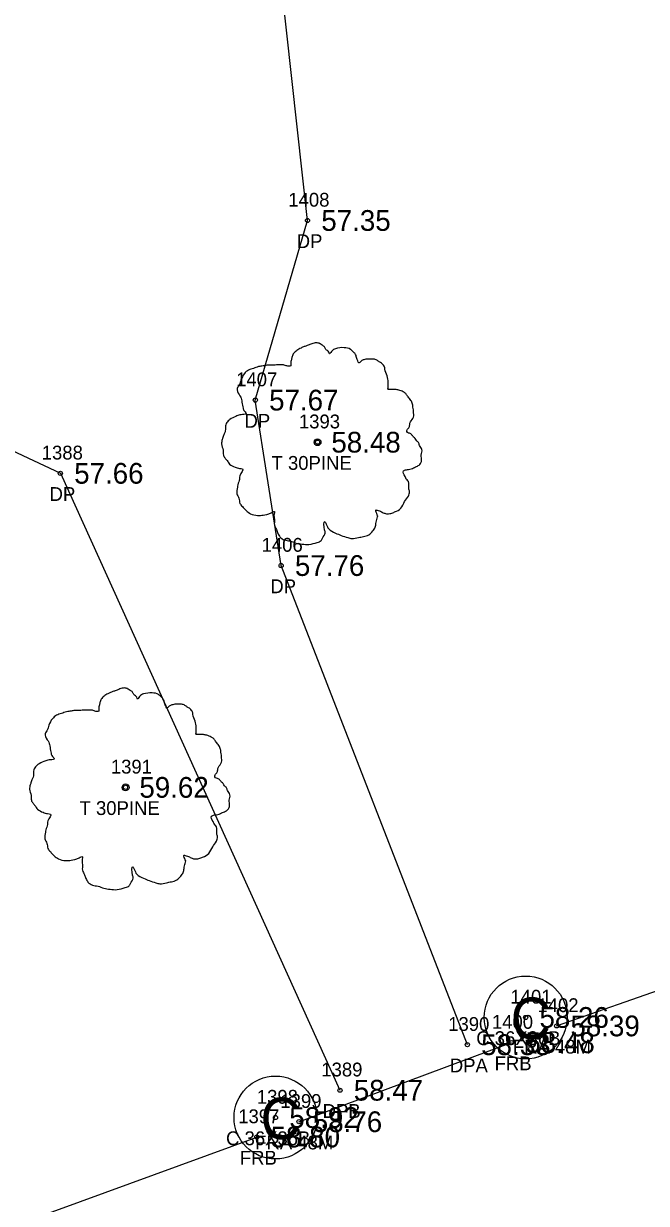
# Model space of a CAD drawing. Extents: x 2420113 to 2422887, y 845323 to 846653.
# Drawn here: x 2421447.4 to 2421492.5, y 845578.5 to 845663.9 of the extents above; entities that cross this region are included whole.
import ezdxf

# ---------------------------------------------------------------- set-up
doc = ezdxf.new("R2010")
doc.units = 0
for name, color, linetype in [('RD_EX_BldgApp', 7, 'Continuous'), ('RD_EX_BldgApp_txCode', 7, 'Continuous'), ('RD_EX_Driveway', 7, 'Continuous'), ('RD_EX_Driveway_txCode', 7, 'Continuous'), ('RD_EX_Fence_Other', 7, 'Continuous'), ('RD_EX_Fence_Other_txCode', 7, 'Continuous'), ('RD_EX_TX_BldgApp_ELEV', 7, 'Continuous'), ('RD_EX_TX_Driveway_ELEV', 7, 'Continuous'), ('RD_EX_TX_Fence_Other_ELEV', 7, 'Continuous'), ('RD_EX_TX_VEG_ELEV', 7, 'Continuous'), ('RD_EX_VEG', 7, 'Continuous'), ('RD_EX_VEG_txCode', 7, 'Continuous'), ('RD_SMD_Locator', 7, 'Continuous')]:
    doc.layers.add(name, color=color, linetype=linetype)

msp = doc.modelspace()

# ---------------------------------------------------------------- linework, layer by layer
at = {"layer": 'RD_EX_BldgApp'}
for centre in [(2421483.774, 845591.992), (2421465.671, 845584.746)]:
    msp.add_circle(centre, 3, dxfattribs=at)
at = {"layer": 'RD_EX_Driveway'}
for points in [[(2421479.556, 845590.019), (2421466.078, 845624.704), (2421464.212, 845636.68), (2421467.989, 845649.684), (2421466.105, 845666.758), (2421462.732, 845676.525), (2421460.587, 845680.29), (2421463.191, 845688.629)], [(2421419.818, 845681.166), (2421427.875, 845673.766), (2421425.446, 845664.821), (2421425.975, 845652.245), (2421431.449, 845642.482), (2421441.096, 845635.605), (2421450.107, 845631.381), (2421470.335, 845586.723)]]:
    msp.add_lwpolyline(points, dxfattribs=at)
at = {"layer": 'RD_EX_Fence_Other'}
for p, q in [((2421486.013, 845591.379), (2421514.277, 845601.287)), ((2421467.372, 845584.444), (2421482.756, 845590.17)), ((2421413.85, 845564.915), (2421464.323, 845583.337))]:
    msp.add_line(p, q, dxfattribs=at)
at = {"layer": 'RD_EX_VEG'}
for centre, radius in [((2421468.715, 845633.634), 0.25), ((2421468.702, 845633.615), 0.0001), ((2421454.824, 845608.648), 0.25), ((2421454.811, 845608.629), 0.0001)]:
    msp.add_circle(centre, radius, dxfattribs=at)
for points in [[(2421468.847, 845640.801), (2421468.547, 845640.826), (2421468.222, 845640.726), (2421467.972, 845640.626), (2421467.747, 845640.551), (2421467.522, 845640.451), (2421467.223, 845640.277), (2421466.998, 845640.077), (2421466.873, 845639.827), (2421466.823, 845639.602), (2421466.773, 845639.327), (2421466.773, 845639.152), (2421466.648, 845639.127), (2421466.498, 845639.152), (2421466.248, 845639.227), (2421465.998, 845639.227), (2421465.748, 845639.227), (2421465.398, 845639.202), (2421465.048, 845639.202), (2421464.774, 845639.152), (2421464.449, 845639.102), (2421464.074, 845638.977), (2421463.724, 845638.852), (2421463.424, 845638.602), (2421463.174, 845638.128), (2421463.049, 845637.778), (2421462.899, 845637.528), (2421463.049, 845637.078), (2421463.224, 845636.728), (2421463.249, 845636.528), (2421463.324, 845636.103), (2421463.424, 845635.879), (2421463.549, 845635.679), (2421463.474, 845635.654), (2421463.099, 845635.604), (2421462.799, 845635.504), (2421462.375, 845635.279), (2421462.15, 845635.054), (2421462.05, 845634.729), (2421462.025, 845634.379), (2421461.925, 845634.179), (2421461.85, 845633.904), (2421461.825, 845633.829), (2421461.775, 845633.505), (2421461.875, 845633.055), (2421461.9, 845632.705), (2421462.025, 845632.48), (2421462.175, 845632.305), (2421462.35, 845632.055), (2421462.749, 845631.83), (2421463.074, 845631.73), (2421463.274, 845631.705), (2421463.099, 845631.206), (2421463.049, 845630.856), (2421462.924, 845630.456), (2421462.924, 845630.381), (2421462.874, 845629.906), (2421463.024, 845629.581), (2421463.099, 845629.206), (2421463.274, 845628.982), (2421463.549, 845628.682), (2421463.874, 845628.457), (2421464.374, 845628.332), (2421464.774, 845628.357), (2421465.348, 845628.532), (2421465.598, 845628.607), (2421465.573, 845628.432), (2421465.598, 845628.057), (2421465.598, 845627.632), (2421465.748, 845627.307), (2421465.848, 845627.032), (2421465.998, 845626.782), (2421466.323, 845626.558), (2421466.723, 845626.483), (2421467.148, 845626.333), (2421467.597, 845626.258), (2421468.097, 845626.233), (2421468.697, 845626.383), (2421468.972, 845626.508), (2421469.072, 845626.683), (2421469.272, 845627.057), (2421469.222, 845627.282), (2421469.247, 845627.882), (2421469.347, 845627.707), (2421469.522, 845627.357), (2421470.021, 845627.057), (2421470.421, 845626.882), (2421470.896, 845626.732), (2421471.196, 845626.658), (2421471.671, 845626.732), (2421472.045, 845626.807), (2421472.42, 845626.932), (2421472.72, 845627.207), (2421472.895, 845627.482), (2421472.945, 845627.757), (2421473.02, 845628.132), (2421473.07, 845628.307)], [(2421473.07, 845628.307), (2421472.995, 845628.482), (2421472.945, 845628.732), (2421473.02, 845628.707), (2421473.195, 845628.657), (2421473.47, 845628.532), (2421473.695, 845628.457), (2421474.02, 845628.482), (2421474.294, 845628.582), (2421474.744, 845628.857), (2421475.019, 845629.331), (2421475.294, 845629.731), (2421475.369, 845630.056), (2421475.319, 845630.281), (2421475.294, 845630.781), (2421475.094, 845631.031), (2421475.044, 845631.156), (2421474.944, 845631.555), (2421475.019, 845631.605), (2421475.294, 845631.655), (2421475.669, 845631.78), (2421475.944, 845631.905), (2421476.169, 845632.08), (2421476.244, 845632.305), (2421476.219, 845632.705), (2421476.269, 845633.105), (2421476.194, 845633.255), (2421476.094, 845633.405), (2421476.019, 845633.605), (2421475.869, 845633.754), (2421475.769, 845633.904), (2421475.669, 845634.004), (2421475.544, 845634.154), (2421475.369, 845634.279), (2421475.219, 845634.329), (2421475.169, 845634.479), (2421475.319, 845634.679), (2421475.369, 845634.779), (2421475.394, 845635.004), (2421475.619, 845635.354), (2421475.669, 845635.754), (2421475.619, 845636.178), (2421475.569, 845636.453), (2421475.419, 845636.728), (2421475.219, 845636.978), (2421475.094, 845637.153), (2421474.919, 845637.278), (2421474.594, 845637.403), (2421474.344, 845637.453), (2421473.995, 845637.453), (2421473.795, 845637.503), (2421473.82, 845637.553), (2421473.82, 845637.703), (2421473.82, 845637.978), (2421473.745, 845638.427), (2421473.595, 845638.927), (2421473.595, 845638.952), (2421473.495, 845639.202), (2421473.27, 845639.402), (2421473.095, 845639.502), (2421472.895, 845639.627), (2421472.645, 845639.652), (2421472.345, 845639.652), (2421472.07, 845639.602), (2421471.87, 845639.502), (2421471.696, 845639.377), (2421471.621, 845639.527), (2421471.521, 845639.827), (2421471.471, 845639.977), (2421471.321, 845640.152), (2421471.096, 845640.352), (2421470.646, 845640.476), (2421470.021, 845640.402), (2421469.721, 845640.202), (2421469.571, 845640.027), (2421469.522, 845640.152), (2421469.322, 845640.352), (2421469.222, 845640.526), (2421469.047, 845640.651), (2421468.897, 845640.751), (2421468.797, 845640.801)], [(2421454.956, 845615.815), (2421454.656, 845615.84), (2421454.331, 845615.74), (2421454.081, 845615.64), (2421453.856, 845615.565), (2421453.631, 845615.465), (2421453.331, 845615.291), (2421453.107, 845615.091), (2421452.982, 845614.841), (2421452.932, 845614.616), (2421452.882, 845614.341), (2421452.882, 845614.166), (2421452.757, 845614.141), (2421452.607, 845614.166), (2421452.357, 845614.241), (2421452.107, 845614.241), (2421451.857, 845614.241), (2421451.507, 845614.216), (2421451.157, 845614.216), (2421450.883, 845614.166), (2421450.558, 845614.116), (2421450.183, 845613.991), (2421449.833, 845613.866), (2421449.533, 845613.616), (2421449.283, 845613.142), (2421449.158, 845612.792), (2421449.008, 845612.542), (2421449.158, 845612.092), (2421449.333, 845611.742), (2421449.358, 845611.542), (2421449.433, 845611.117), (2421449.533, 845610.893), (2421449.658, 845610.693), (2421449.583, 845610.668), (2421449.208, 845610.618), (2421448.908, 845610.518), (2421448.484, 845610.293), (2421448.259, 845610.068), (2421448.159, 845609.743), (2421448.134, 845609.393), (2421448.034, 845609.193), (2421447.959, 845608.918), (2421447.934, 845608.843), (2421447.884, 845608.519), (2421447.984, 845608.069), (2421448.009, 845607.719), (2421448.134, 845607.494), (2421448.284, 845607.319), (2421448.459, 845607.069), (2421448.858, 845606.844), (2421449.183, 845606.744), (2421449.383, 845606.719), (2421449.208, 845606.22), (2421449.158, 845605.87), (2421449.033, 845605.47), (2421449.033, 845605.395), (2421448.983, 845604.92), (2421449.133, 845604.595), (2421449.208, 845604.22), (2421449.383, 845603.996), (2421449.658, 845603.696), (2421449.983, 845603.471), (2421450.483, 845603.346), (2421450.883, 845603.371), (2421451.457, 845603.546), (2421451.707, 845603.621), (2421451.682, 845603.446), (2421451.707, 845603.071), (2421451.707, 845602.646), (2421451.857, 845602.321), (2421451.957, 845602.046), (2421452.107, 845601.796), (2421452.432, 845601.572), (2421452.832, 845601.497), (2421453.256, 845601.347), (2421453.706, 845601.272), (2421454.206, 845601.247), (2421454.806, 845601.397), (2421455.081, 845601.522), (2421455.181, 845601.697), (2421455.381, 845602.071), (2421455.331, 845602.296), (2421455.356, 845602.896), (2421455.455, 845602.721), (2421455.63, 845602.371), (2421456.13, 845602.071), (2421456.53, 845601.896), (2421457.005, 845601.746), (2421457.305, 845601.672), (2421457.779, 845601.746), (2421458.154, 845601.821), (2421458.529, 845601.946), (2421458.829, 845602.221), (2421459.004, 845602.496), (2421459.054, 845602.771), (2421459.129, 845603.146), (2421459.179, 845603.321)], [(2421459.179, 845603.321), (2421459.104, 845603.496), (2421459.054, 845603.746), (2421459.129, 845603.721), (2421459.304, 845603.671), (2421459.579, 845603.546), (2421459.804, 845603.471), (2421460.128, 845603.496), (2421460.403, 845603.596), (2421460.853, 845603.871), (2421461.128, 845604.345), (2421461.403, 845604.745), (2421461.478, 845605.07), (2421461.428, 845605.295), (2421461.403, 845605.795), (2421461.203, 845606.045), (2421461.153, 845606.17), (2421461.053, 845606.569), (2421461.128, 845606.619), (2421461.403, 845606.669), (2421461.778, 845606.794), (2421462.053, 845606.919), (2421462.278, 845607.094), (2421462.352, 845607.319), (2421462.328, 845607.719), (2421462.377, 845608.119), (2421462.303, 845608.269), (2421462.203, 845608.419), (2421462.128, 845608.619), (2421461.978, 845608.768), (2421461.878, 845608.918), (2421461.778, 845609.018), (2421461.653, 845609.168), (2421461.478, 845609.293), (2421461.328, 845609.343), (2421461.278, 845609.493), (2421461.428, 845609.693), (2421461.478, 845609.793), (2421461.503, 845610.018), (2421461.728, 845610.368), (2421461.778, 845610.768), (2421461.728, 845611.192), (2421461.678, 845611.467), (2421461.528, 845611.742), (2421461.328, 845611.992), (2421461.203, 845612.167), (2421461.028, 845612.292), (2421460.703, 845612.417), (2421460.453, 845612.467), (2421460.103, 845612.467), (2421459.904, 845612.517), (2421459.929, 845612.567), (2421459.929, 845612.717), (2421459.929, 845612.992), (2421459.854, 845613.441), (2421459.704, 845613.941), (2421459.704, 845613.966), (2421459.604, 845614.216), (2421459.379, 845614.416), (2421459.204, 845614.516), (2421459.004, 845614.641), (2421458.754, 845614.666), (2421458.454, 845614.666), (2421458.179, 845614.616), (2421457.979, 845614.516), (2421457.804, 845614.391), (2421457.729, 845614.541), (2421457.63, 845614.841), (2421457.58, 845614.991), (2421457.43, 845615.166), (2421457.205, 845615.366), (2421456.755, 845615.49), (2421456.13, 845615.416), (2421455.83, 845615.216), (2421455.68, 845615.041), (2421455.63, 845615.166), (2421455.43, 845615.366), (2421455.331, 845615.54), (2421455.156, 845615.665), (2421455.006, 845615.765), (2421454.906, 845615.815)]]:
    msp.add_spline(points, degree=3, dxfattribs=at)
at = {"layer": 'RD_SMD_Locator'}
for centre in [(2421467.989, 845649.684), (2421464.212, 845636.68), (2421468.715, 845633.634), (2421450.107, 845631.381), (2421466.078, 845624.704), (2421454.824, 845608.648), (2421483.774, 845591.992), (2421486.013, 845591.379), (2421479.556, 845590.019), (2421482.756, 845590.17), (2421470.335, 845586.723), (2421465.671, 845584.746), (2421467.372, 845584.444), (2421464.323, 845583.337)]:
    msp.add_circle(centre, 0.15, dxfattribs=at)

# ---------------------------------------------------------------- texts
at = {"layer": 'RD_EX_BldgApp'}
for p in [(2421482.693, 845590.431), (2421464.59, 845583.184)]:
    msp.add_text('C', height=3, dxfattribs=at).set_placement(p)
at = {"layer": 'RD_EX_BldgApp_txCode'}
for s, p in [('1401', (2421482.671, 845592.992)), ('C 36X36B', (2421480.199, 845589.992)), ('1398', (2421464.324, 845585.746)), ('C 36X36B', (2421462.096, 845582.746))]:
    msp.add_text(s, height=1, dxfattribs=at).set_placement(p)
at = {"layer": 'RD_EX_Driveway_txCode'}
for s, p in [('1408', (2421466.603, 845650.684)), ('DP', (2421467.21, 845647.684)), ('1407', (2421462.826, 845637.68)), ('DP', (2421463.432, 845634.68)), ('1388', (2421448.761, 845632.381)), ('DP', (2421449.328, 845629.381)), ('1406', (2421464.669, 845625.704)), ('DP', (2421465.299, 845622.704)), ('1390', (2421478.17, 845591.019)), ('DPA', (2421478.288, 845588.019)), ('1389', (2421468.989, 845587.723)), ('DPB', (2421469.083, 845584.723))]:
    msp.add_text(s, height=1, dxfattribs=at).set_placement(p)
at = {"layer": 'RD_EX_Fence_Other_txCode'}
for s, p in [('1402', (2421484.627, 845592.379)), ('1400', (2421481.331, 845591.17)), ('FRA 48M', (2421482.847, 845589.379)), ('FRB', (2421481.528, 845588.17)), ('1399', (2421466.026, 845585.444)), ('1397', (2421462.977, 845584.337)), ('FRA 48M', (2421464.207, 845582.444)), ('FRB', (2421463.095, 845581.337))]:
    msp.add_text(s, height=1, dxfattribs=at).set_placement(p)
at = {"layer": 'RD_EX_TX_BldgApp_ELEV'}
for s, p in [('58.26', (2421484.774, 845591.242)), ('58.92', (2421466.671, 845583.996))]:
    msp.add_text(s, height=1.5, dxfattribs=at).set_placement(p)
at = {"layer": 'RD_EX_TX_Driveway_ELEV'}
for s, p in [('57.35', (2421468.989, 845648.934)), ('57.67', (2421465.212, 845635.93)), ('57.66', (2421451.107, 845630.631)), ('57.76', (2421467.078, 845623.954)), ('58.33', (2421480.556, 845589.269)), ('58.47', (2421471.335, 845585.973))]:
    msp.add_text(s, height=1.5, dxfattribs=at).set_placement(p)
at = {"layer": 'RD_EX_TX_Fence_Other_ELEV'}
for s, p in [('58.39', (2421487.013, 845590.629)), ('58.48', (2421483.756, 845589.42)), ('58.76', (2421468.372, 845583.694)), ('58.80', (2421465.323, 845582.587))]:
    msp.add_text(s, height=1.5, dxfattribs=at).set_placement(p)
at = {"layer": 'RD_EX_TX_VEG_ELEV'}
for s, p in [('58.48', (2421469.715, 845632.884)), ('59.62', (2421455.824, 845607.898))]:
    msp.add_text(s, height=1.5, dxfattribs=at).set_placement(p)
at = {"layer": 'RD_EX_VEG_txCode'}
for s, p in [('1393', (2421467.368, 845634.634)), ('T 30PINE', (2421465.388, 845631.634)), ('1391', (2421453.761, 845609.648)), ('T 30PINE', (2421451.497, 845606.648))]:
    msp.add_text(s, height=1, dxfattribs=at).set_placement(p)

doc.saveas('drawing.dxf')
